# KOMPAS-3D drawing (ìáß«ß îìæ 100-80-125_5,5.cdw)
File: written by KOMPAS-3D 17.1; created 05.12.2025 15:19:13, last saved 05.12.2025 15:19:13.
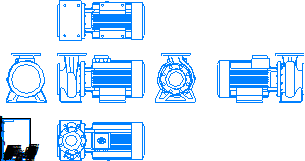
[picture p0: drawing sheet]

Sheet 1: A4, portrait

Title block, sheet 1: name: Насос МНС / 100-80-125_5,5; material: Сталь 10  ГОСТ 1050-88; mass: 185,42; sheets: 1; sheet format: A4

Views: Вид 1, Спереди, Проекционный вид 2, Проекционный вид 3, Проекционный вид 4, Проекционный вид 5, Проекционный вид 6
Referenced files in \\adlc.lan\data\АДЛ_ПКД\3D-модели\ADL production\Насосы ГРАНПАМП\Насосы ГРАНПАМП серии МНС\KOMPAS 3D\: Насос МНС 100-80-125_5,5.m3d
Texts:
  Andrey
  АДЛ
Dimensions and other numbers on the sheet: 1:1; 1; 100-80-125_5,5; 185,42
